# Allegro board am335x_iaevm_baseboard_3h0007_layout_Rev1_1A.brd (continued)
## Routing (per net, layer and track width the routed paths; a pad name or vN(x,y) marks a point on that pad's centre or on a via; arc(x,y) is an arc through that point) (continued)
AM335X_GPMC_AD7: length 84.1
  TOP w0.102: v2(90.6,84.2) U2.T9
  TOP w0.121: v1(141.13,94.04) 140.52,93.43 138.19,93.43 137.24,92.48 132.39,92.48 131.89,91.98 129.64,91.98 128.86,92.76 117.14,92.76 115.23,90.85 108.65,90.85 108.64,90.86 106.32,90.86 106.31,90.85 103.34,90.85 103.27,90.79 98.74,90.79 98.44,91.09 v1(98.41,91.09) ; R157.1 v1(140.63,115.73)
  LY4 w0.133: v1(98.41,91.09) 97.19,89.87 97.19,89.14 95.93,87.87 95.11,87.05 93.18,87.05 93.12,87 90.44,87 90.2,86.76 90.2,86.46 90.2,86.45 90.2,86.44 89.96,86.2 89.95,86.2 89.4,85.65 89.4,85.64 89.14,85.38 89.14,84.62 89.4,84.36 89.4,84.06 89.4,84.06 89.4,84.04 89.64,83.8 89.66,83.8 89.66,83.8 90.2,83.8 v2(90.6,84.2)
  BOTTOM w0.121: v1(141.13,94.04) 141.13,94.27 141.29,94.43 141.29,98.29 140.61,98.98 140.61,101.4 141.54,102.33 141.54,111.8 140.63,112.71 v1(140.63,115.73)
AM335X_GPMC_AD8: length 30.8
  TOP w0.102: U2.U10 91,85.41 91.35,85.76 93,85.76
  TOP w0.121: R261.2 104.94,91.1 103.28,91.1 v1(103.03,91.35) ; v1(94.02,86.35) 93.8,86.13 93.51,86.13 93.14,85.76 93,85.76
  LY3 w0.133: v1(94.02,86.35) 94.52,85.85 98.39,85.85 98.4,85.85 101.48,85.85 101.61,85.98 101.61,86.35 101.48,86.47 97.14,86.47 97.01,86.6 97.01,87.06 97.14,87.18 101.03,87.18 101.15,87.31 101.15,88.38 101.28,88.51 101.51,88.51 101.64,88.63 101.64,89.93 101.76,90.05 102.91,90.05 103.03,90.18 v1(103.03,91.35)
AM335X_GPMC_AD9: length 22.7
  TOP w0.102: U2.T10 v2(90.6,85)
  TOP w0.121: v1(102.4,91.6) 102.7,91.91 103.34,91.91 R263.2
  LY3 w0.133: v1(102.4,91.6) 102.72,91.92 103.35,91.92 103.48,91.79 103.48,87.78 103.35,87.66 103.26,87.66 103.14,87.53 103.14,86.71 102.01,85.59 99.66,85.59 99.66,85.59 94.86,85.59 94.27,85 93.69,85 93.46,85.23 90.73,85.23 90.6,85.1 v2(90.6,85)
AM335X_GPMC_AD10: length 21.8
  TOP w0.102: U2.T11 v2(90.6,86.6)
  TOP w0.121: R150.2 v1(110.17,86.78)
  BOTTOM w0.102: 93.47,86.79 92.9,86.22 91.22,86.22 90.84,86.6 v2(90.6,86.6)
  BOTTOM w0.121: v1(110.17,86.78) 109.84,86.45 104.86,86.45 104.66,86.65 96.81,86.65 96.32,87.14 95.66,87.14 95.31,86.79 93.47,86.79
AM335X_GPMC_AD11: length 45
  TOP w0.102: U2.U12 91.01,87 91.41,87.4 v2(92.2,87.4)
  TOP w0.121: v1(108.67,86.99) 108.57,86.89 108.57,84.87 108.83,84.62 109.77,84.62 R243.2
  BOTTOM w0.102: 93,87.02 92.77,86.79 92.34,86.79 92.2,86.93 v2(92.2,87.4)
  BOTTOM w0.121: v1(108.67,86.99) 108.67,88.58 108.8,88.71 109.54,88.71 109.66,88.84 109.66,90.05 109.54,90.18 107.5,90.18 107.38,90.05 107.38,86.85 107.25,86.73 105.27,86.73 105.14,86.85 105.14,88.46 105.02,88.58 104.63,88.58 104.51,88.46 104.51,87.78 104.38,87.65 103.97,87.65 103.85,87.78 103.85,88.66 103.72,88.78 103.39,88.78 103.26,88.66 103.26,87.78 103.14,87.65 102.78,87.65 102.65,87.78 102.65,88.36 102.53,88.49 98.36,88.49 98.23,88.36 98.23,87.9 98.36,87.77 100.79,87.77 100.91,87.64 100.91,87.31 100.79,87.18 97.19,87.18 97.03,87.34 97.03,88.37 96.91,88.5 95.99,88.5 95.87,88.37 95.87,87.85 95.74,87.73 95.31,87.73 94.86,87.28 93.26,87.28 93,87.02
AM335X_GPMC_AD12: length 45.1
  TOP w0.102: U2.T12 v2(90.6,87.4)
  TOP w0.121: v1(111.39,87.13) 111.75,86.78 R152.2
  LY4 w0.133: v1(101.69,88.05) 101.69,87.98 101.81,87.86 105.14,87.86 105.27,87.98 105.27,88.51 105.14,88.63 101.81,88.63 101.69,88.76 101.69,89.14 101.81,89.27 108.19,89.27 108.32,89.14 108.32,88.63 108.19,88.51 107.38,88.51 107.25,88.38 107.25,87.77 107.38,87.64 109.95,87.64 110.08,87.77 110.08,89.83 109.95,89.95 109.28,89.95 109.16,90.08 109.16,90.54 109.28,90.66 110.81,90.66 111.07,90.4 111.07,87.45 v1(111.39,87.13)
  BOTTOM w0.102: 92.75,86.55 91.45,86.55 v2(90.6,87.4)
  BOTTOM w0.121: v1(101.69,88.05) 101.28,87.64 101.28,87.06 101.12,86.9 96.91,86.9 96.79,87.03 96.79,88.1 96.66,88.23 96.24,88.23 96.12,88.1 96.12,87.61 95.99,87.48 95.43,87.48 94.99,87.04 93.37,87.04 92.88,86.55 92.75,86.55
AM335X_GPMC_AD13: length 21.8
  TOP w0.102: v2(89.8,87.4) U2.R12
  TOP w0.121: v1(96.48,90.38) 96.53,90.38 97.04,89.88 R247.2
  BOTTOM w0.102: 93,88.71 92.9,88.71 92.77,88.58 92.77,87.97 92.65,87.84 92.26,87.84 92.14,87.97 92.14,88.84 92.01,88.96 91.35,88.96 91.22,88.84 91.22,87.95 91.1,87.82 90.21,87.82 89.8,87.41 v2(89.8,87.4)
  BOTTOM w0.121: v1(96.48,90.38) 96.48,91.41 96.61,91.53 98.67,91.53 98.79,91.66 98.79,92.21 98.67,92.34 96.1,92.34 95.52,91.76 95.52,88.43 94.93,87.84 94.04,87.84 93.92,87.97 93.92,88.58 93.79,88.71 93,88.71
AM335X_GPMC_AD14: length 12.3
  TOP w0.102: U2.V13 92.83,87.8 93,87.97
  TOP w0.121: 93,87.97 93,87.97 94.78,87.97 95.77,88.97 95.77,90.79 98.14,93.16 99.23,93.16 100.34,94.27 R248.2
AM335X_GPMC_AD15: length 10.6
  TOP w0.102: U2.U13 91.42,88.22 93,88.22
  TOP w0.121: 93,88.22 94.68,88.22 95.53,89.07 95.53,90.95 96.56,91.99 96.56,93.46 R253.2
AM335X_GPMC_ADVN_ALE: length 62.6
  TOP w0.102: v2(89.8,82.6) U2.R7
  TOP w0.121: v1(139.51,97.67) 140.12,98.28 R137.2
  BOTTOM w0.102: v2(89.8,82.6) 89.8,82.55 90.17,82.18 91.27,82.18
  BOTTOM w0.121: 91.27,82.18 91.86,82.77 96.01,82.77 98,84.75 98,85.15 98.02,85.18 98.02,85.19 98.24,85.41 98.63,85.41 98.83,85.21 111.71,85.21 115.17,88.67 115.58,88.67 129.12,88.67 129.88,89.43 131.09,89.43 131.68,88.84 137.4,88.84 138.79,90.24 138.79,96.96 v1(139.51,97.67)
AM335X_GPMC_BE0N_CLE: length 59.3
  TOP w0.102: v2(90.6,81.8) U2.T6
  TOP w0.121: R136.2 140.12,95.72 v1(139.61,95.21)
  BOTTOM w0.102: 91.92,82.52 91.2,81.8 v2(90.6,81.8)
  BOTTOM w0.121: 91.92,82.52 96.11,82.52 97.29,83.7 97.79,83.7 98.81,84.72 112.19,84.72 115.64,88.18 129.32,88.18 130.09,88.94 130.77,88.94 131.36,88.35 137.6,88.35 139.29,90.03 139.29,94.89 v1(139.61,95.21)
AM335X_GPMC_BE1N: length 79.9
  TOP w0.102: 91,92.9 U2.U18
  TOP w0.121: 91,92.9 91,93.59 92.83,95.42 94.83,95.42 95.06,95.64 v1(96.18,95.64) ; v1(97.62,141.9) 97.57,141.95 R577.2
  LY4 w0.133: v1(96.18,95.64) 96.18,97.98 95.87,98.28 95.87,111.09 96,111.21 96.4,111.21 96.53,111.09 96.53,104.23 96.66,104.1 97.01,104.1 97.14,104.23 97.14,111.72 97.01,111.85 96.4,111.85 96.26,112 96.26,114.04 95.67,114.63 95.67,128.92 95.03,129.55 95.03,140.75 94.8,140.98 93,140.98 92.87,141.11 92.87,143.04 93,143.17 96.35,143.17 v1(97.62,141.9)
AM335X_GPMC_CLK: length 73.4
  TOP w0.102: 93.89,87.54 93.26,87.54 92.72,87 U2.V12
  TOP w0.121: R572.2 116.69,95.36 116.81,95.49 117.26,95.49 117.39,95.62 117.39,96 117.26,96.13 116.32,96.13 116.19,96 116.19,95.54 116.06,95.41 115.78,95.41 115.66,95.54 115.66,96 115.53,96.13 115.1,96.13 114.98,96 114.98,94.55 114.85,94.42 114.46,94.42 114.34,94.55 114.34,96 114.21,96.13 113.7,96.13 113.58,96 113.58,94.55 113.45,94.42 112.97,94.42 112.84,94.55 112.84,96 112.71,96.13 112.36,96.13 112.23,96 112.23,94.55 112.1,94.42 111.67,94.42 111.54,94.55 111.54,96 111.42,96.13 111.06,96.13 110.93,96 110.93,94.55 110.81,94.42 110.5,94.42 110.37,94.55 110.37,96 110.25,96.13 109.92,96.13 109.79,96 109.79,94.53 109.66,94.4 109.42,94.4 109.29,94.53 109.29,96 109.16,96.13 107.89,96.13 107.76,96 107.76,95.41 107.89,95.29 108.19,95.29 108.32,95.16 108.32,94.52 108.19,94.39 107.3,94.39 107.17,94.52 107.17,96 107.05,96.13 106.72,96.13 106.59,96 106.59,94.52 106.46,94.39 106.13,94.39 106,94.52 106,95.99 105.87,96.11 105.24,96.11 105.12,95.99 105.12,94.01 104.99,93.88 104.61,93.88 104.48,94.01 104.48,95.92 104.35,96.05 104.02,96.05 103.89,95.92 103.89,94.18 103.77,94.05 103.44,94.05 103.31,94.18 103.31,94.58 103.19,94.7 102.88,94.7 102.75,94.58 102.75,93.18 102.88,93.05 103.35,93.05 103.47,92.92 103.47,92.39 103.35,92.27 101.76,92.27 101.64,92.14 100.04,92.14 99.91,92.01 99.91,91.73 100.04,91.6 101.61,91.6 101.74,91.48 101.74,91.16 101.61,91.04 99.5,91.04 99.38,91.16 99.38,92.7 99.25,92.82 98.97,92.82 98.84,92.7 98.84,91.66 98.72,91.53 98.39,91.53 98.26,91.66 98.26,92.24 98.13,92.37 97.75,92.37 97.62,92.24 97.62,91.66 97.5,91.53 96.92,91.53 96.02,90.64 96.02,88.48 95.34,87.8 95.34,87.51 95.11,87.29 94.59,87.29 94.34,87.54 93.89,87.54
AM335X_GPMC_CS0N: length 58.4
  TOP w0.102: 93,82.2 U2.V6
  TOP w0.121: 93,82.2 93.06,82.26 95.79,82.26 98.44,84.91 v1(98.44,84.97) ; R183.2 140.12,96.99 v1(139.56,96.43)
  BOTTOM w0.121: v1(139.56,96.43) 139.04,95.91 139.04,90.13 137.5,88.59 131.57,88.59 130.98,89.18 129.98,89.18 129.22,88.42 115.47,88.42 115.27,88.42 111.81,84.97 98.73,84.97 98.72,84.97 v1(98.44,84.97)
AM335X_GPMC_CS1N: length 13.3
  TOP w0.102: U2.U9 91.01,84.6 91.41,85 92.19,85
  TOP w0.121: R175.1 99.99,89.6 v1(100.42,90.03) ; 92.19,85 92.34,84.85 94.96,84.85 v1(95.25,85.14)
  LY4 w0.133: v1(95.25,85.14) 95.25,85.28 97.93,87.96 99.18,87.96 99.66,88.43 99.66,89.27 v1(100.42,90.03)
AM335X_GPMC_CS2N: length 16.9
  TOP w0.121: R173.1 100.49,92.87 v1(100.49,93.41) ; v1(95.38,84.2) 95.38,84.21 95.35,84.24 95.35,84.34 95.09,84.6 U2.V9
  LY4 w0.133: v1(100.49,93.41) 100.49,91.91 100.87,91.54 100.87,89.17 99.16,87.46 97.94,87.46 95.92,85.44 95.92,84.74 v1(95.38,84.2)
AM335X_GPMC_CS3N: length 75.5
  TOP w0.102: v2(90.6,88.2) U2.T13
  TOP w0.121: v1(94.93,145.78) 94.88,145.83 93.94,145.83 R573.2
  LY4 w0.102: v2(90.6,88.2) 93.3,88.2
  LY4 w0.133: 93.3,88.2 93.4,88.3 95.38,88.3 96.03,88.95 96.03,90.57 96.75,91.29 97.97,91.29 99.48,92.79 99.48,93.64 100.05,94.2 100.05,100.59 100.95,101.5 100.95,116.99 102.04,118.08 102.04,120.01 101.54,120.51 101.54,132.85 101.42,132.98 99.4,132.98 99.27,133.11 99.27,135.62 99.4,135.75 101.24,135.75 101.54,136.05 101.54,140.79 97.12,145.22 95.49,145.22 v1(94.93,145.78)
AM335X_GPMC_OEN_REN: length 67.8
  TOP w0.102: v2(90.6,82.6) U2.T7
  TOP w0.121: R134.2 140.11,104.16 v1(140.11,103.47)
  BOTTOM w0.102: v2(90.6,82.6) 91.02,83.02 93,83.02
  BOTTOM w0.121: 93,83.02 95.91,83.02 97.75,84.86 97.75,85.26 97.76,85.27 97.76,85.38 98.04,85.66 98.73,85.66 98.93,85.46 111.61,85.46 115.06,88.92 115.68,88.92 129.02,88.92 129.78,89.68 131.25,89.68 131.84,89.09 137.3,89.09 138.55,90.34 138.55,98.61 137.81,99.35 137.81,100.42 140.11,102.72 v1(140.11,103.47)
AM335X_GPMC_WAIT: length 61
  TOP w0.102: U2.T17 90.24,91 90.59,91.35 90.59,92.9
  TOP w0.121: 90.59,92.9 90.59,93.89 92.37,95.67 93.59,95.67 94.2,96.27 94.2,97.08 95.26,98.14 95.26,100.94 95.87,101.56 107.78,101.56 108.01,101.33 124.14,101.33 125.34,102.53 130.47,102.53 131.74,103.8 131.74,104.46 132.49,105.21 136.24,105.21 137.6,103.85 138.71,103.85 138.89,103.67 139.23,103.67 R179.2
AM335X_GPMC_WEN: length 70
  TOP w0.102: U2.U6 91.03,82.2 91.41,82.59 92.08,82.59
  TOP w0.121: 92.08,82.59 92.16,82.51 95.68,82.51 96.49,83.32 96.49,84.23 v1(96.51,84.24) ; R138.2 v1(139.61,104.99)
  BOTTOM w0.121: v1(139.61,104.99) 139.1,104.48 139.1,102.76 137.01,100.68 137.01,98.97 137.63,98.35 137.63,92.09 137.8,91.91 137.8,90.65 136.99,89.83 132.29,89.83 131.7,90.42 129.47,90.42 128.71,89.66 114.76,89.66 111.3,86.2 99.24,86.2 99.04,86.4 97.68,86.4 97.55,86.28 96.31,86.28 96,85.97 95.99,85.97 95.8,85.77 95.8,84.94 96.49,84.25 96.51,84.25 v1(96.51,84.24)
AM335X_GPMC_WPN: length 55.7
  TOP w0.102: U2.U17 91.38,91.38 91.38,92.9
  TOP w0.121: R180.2 139.61,102.02 137.83,102.02 137.39,102.46 137.39,102.69 137.16,102.92 132.71,102.92 130.05,100.25 129.91,100.11 114.34,100.11 112.81,98.58 104.23,98.58 102.45,96.8 98.07,96.8 96.44,95.17 95.32,95.17 94.86,94.7 93.1,94.7 91.38,92.98 91.38,92.9
AM335X_I2C0_SCL: length 201.1
  TOP w0.102: v2(79.4,90.6) U2.C16
  TOP w0.121: R265.2 145.33,71.28 143.93,71.28 142.66,72.55 141.52,72.55 140.94,71.98 U7.6 140.94,68.76 140.52,68.34 126.02,68.34 120.41,62.73 120.41,59.81 116.97,56.36 107.29,56.36 105.51,54.58 100.99,54.58 100.93,54.52 100.57,54.52 100.5,54.58 97.98,54.58 97.22,53.82 96.07,53.82 95.34,53.08 85.72,53.08 85.3,52.67 83.9,52.67 83.39,53.18 80.65,53.18 80.02,53.82 79.02,53.82 v1(78.57,53.37) 78.13,53.37 77.94,53.18 74.63,53.18 73.05,54.76 73.05,55.35 72.5,55.9 72.13,55.9 71.72,55.9 71.07,55.25 66.59,55.25 64.48,57.35 64.34,57.5 61.63,57.5 60.24,58.89 v1(60.24,59.79) ; v1(77.86,95.41) 75.48,95.41 75.07,95.82 73.49,95.82 72.96,95.29 71.74,95.29 69.69,97.35 66.37,97.35 65.42,97.35 64.82,96.75 62.81,96.75 62.62,96.94 v1(62.01,96.94)
  LY4 w0.133: v1(80.68,25.56) 80.68,26.07 81.31,26.7 81.31,36.25 80.8,36.76 80.8,43.24 78.77,45.27 78.77,53.18 v1(78.57,53.37)
  BOTTOM w0.102: v2(79.4,90.6) 79.4,90.6 79.79,90.99 79.79,92.9
  BOTTOM w0.121: R551.2 81.19,25.06 v1(80.68,25.56) ; 79.79,92.9 79.79,94.23 78.94,95.08 78.17,95.08 77.86,95.39 v1(77.86,95.41) 78.29,95.84 78.29,96.84 78.52,97.07 ; v1(60.24,59.79) 60.55,60.11 60.55,61.12 60.36,61.31 60.36,69.22 63.32,72.17 63.61,72.46 63.61,81.42 63.22,81.8 63.22,83.05 62.56,83.71 62.56,86.8 61.84,87.52 61.84,88.66 60.74,89.76 60.74,91.1 61.51,91.86 61.51,96.15 62.01,96.66 v1(62.01,96.94)
AM335X_I2C0_SDA: length 210
  TOP w0.102: 79.67,93.1 79.67,92.14 79.41,91.88 79.41,91.39 U2.C17
  TOP w0.121: 79.67,93.1 79.67,94.33 79.03,94.97 79.03,95.27 78.18,96.13 v1(77.84,96.13) 77.81,96.13 77.35,95.66 75.97,95.66 75.55,96.07 73.39,96.07 72.86,95.55 72.24,95.55 72.23,95.54 71.85,95.54 69.79,97.6 66.47,97.6 65.18,97.6 64.59,97.01 63.28,97.01 62.79,97.5 61.89,97.5 61.51,97.13 58.88,97.13 55.79,94.05 v1(54.52,94.05) ; v1(54.52,60.04) 54.53,60.04 59.09,60.04 59.6,59.52 59.6,59.09 61.44,57.25 64.24,57.25 66.5,54.98 71.15,54.98 71.82,55.65 72.39,55.65 72.8,55.25 72.8,54.66 73.06,54.39 74.52,52.93 79.15,52.93 v1(79.59,53.37) 79.84,53.12 80.15,53.12 80.34,52.93 83.29,52.93 83.8,52.42 85.5,52.42 85.92,52.84 95.45,52.84 96.18,53.57 97.32,53.57 98.09,54.34 100.4,54.34 100.46,54.28 105.55,54.28 107.39,56.11 117.18,56.11 120.66,59.6 120.66,62.29 126.45,68.08 141.77,68.08 142.21,68.53 U7.5 142.21,71.98 142.4,72.17 142.66,72.17 143.8,71.03 145.33,71.03 R268.2
  LY4 w0.133: v1(79.59,53.37) 79.03,52.82 79.03,45.38 81.06,43.34 81.06,36.87 81.57,36.36 v1(81.57,25.82)
  BOTTOM w0.121: R550.2 81.95,26.2 v1(81.57,25.82) ; v1(77.84,96.13) 77.84,96.61 77.38,97.07 ; v1(54.52,94.05) 54.52,91.6 55.32,90.8 55.32,88.16 54.04,86.88 54.04,85.99 53.44,85.39 53.44,80.68 51.6,78.84 51.6,74.65 54.71,71.54 54.71,60.23 v1(54.52,60.04)
AM335X_LCD_AC_BIAS_EN: length 68.7
  TOP w0.102: v2(89.8,81.8) U2.R6
  TOP w0.121: v1(97.45,83.22) 97.79,83.57 99.07,83.57 v1(99.41,83.23) ; R273.2 127.16,75.22 125.77,75.22 v1(125.77,75.21)
  BOTTOM w0.102: 93.72,80.76 93.71,80.76 91.65,80.76 90.99,81.42 90.44,81.42 90.06,81.8 v2(89.8,81.8)
  BOTTOM w0.121: v1(97.45,83.22) 96.48,82.26 94.73,82.26 94.14,81.68 94.14,81.19 93.72,80.76 ; v1(125.77,75.21) 124.5,75.21 124.37,75.34 124.37,77.63 125.33,78.59 125.33,79.09 125.01,79.41 124.37,79.41 123.74,80.05 123.74,82.99 123.61,83.12 122.64,83.12 122.52,82.99 122.52,81.98 122.39,81.85 113.04,81.85 112.91,81.98 112.91,82.36 113.04,82.49 121.32,82.49 121.45,82.61 121.45,82.99 121.32,83.12 105.85,83.12 105.73,83.25 105.73,83.35 105.6,83.48 99.66,83.48 v1(99.41,83.23)
AM335X_LCD_DATA0: length 118.9
  TOP w0.102: 92.92,77.38 91.94,77.38 91.93,77.37 90.78,77.37 90.51,77.63 90.01,77.63 89.45,78.2 U2.R1
  TOP w0.121: v1(136.26,71.03) 135.81,70.59 118.32,70.59 118.11,70.8 113.63,70.8 112.17,72.26 106.46,72.26 104.92,73.79 98.79,73.79 96.35,76.23 95.68,76.23 94.53,77.38 92.92,77.38 ; SW3.16 v1(162.5,69.13) ; R240.2 141.38,86.52 142.65,86.52 v1(142.66,86.52) 146.29,86.52 146.67,86.91 151.26,86.91 151.58,86.59 153.01,86.59 153.96,87.54 v1(166.53,87.54)
  BOTTOM w0.121: v1(142.66,86.52) 142.15,86.52 141.29,85.67 141.29,80.49 138.27,77.46 138.27,74.75 135.83,72.32 135.83,71.47 135.87,71.43 135.87,71.42 v1(136.26,71.03) ; v1(166.53,87.54) 166.53,87.41 166.09,86.97 166.09,84.54 166.34,84.29 166.34,73.79 165.42,72.87 164.32,72.87 164.06,72.61 164.06,69.57 R96.1 v1(162.5,69.13)
AM335X_LCD_DATA1: length 115.6
  TOP w0.102: U2.R2 89.4,78.76 89.87,78.29 89.87,78.06 90.08,77.85 90.6,77.85 90.84,77.61 92.15,77.61 92.15,77.61
  TOP w0.121: v1(161.45,88.18) 161.38,88.1 153.71,88.1 153.68,88.07 143.06,88.07 v1(142.53,87.54) 142.53,87.54 141.38,87.54 R241.2 ; SW3.15 v1(162.5,66.59) ; v1(135.42,71.03) 134.96,71.03 134.81,70.88 118.74,70.88 118.55,71.07 113.73,71.07 112.31,72.5 106.56,72.5 105.02,74.04 98.89,74.04 96.45,76.48 95.81,76.48 94.59,77.7 92.89,77.7 92.8,77.61 92.16,77.61 92.15,77.61 92.15,77.61
  BOTTOM w0.102: 138.02,74.85 135.6,72.43 135.6,71.51 135.42,71.33
  BOTTOM w0.121: v1(135.42,71.03) 135.42,71.33 ; v1(161.45,88.18) 161.45,84.23 161.51,84.17 161.51,83.92 162.02,83.42 162.02,82.45 161.52,81.95 161.52,67.56 v1(162.5,66.59) R97.1 ; v1(142.53,87.54) 141.05,86.05 141.05,80.59 138.02,77.57 138.02,74.85
AM335X_LCD_DATA2: length 121.9
  TOP w0.102: v2(89.8,79.4) U2.R3
  TOP w0.121: v1(136.79,71.91) 136.49,71.91 136.36,72.04 136.36,72.3 136.23,72.43 135.72,72.43 135.6,72.3 135.6,71.97 135.47,71.84 135.04,71.84 134.91,71.97 134.91,72.3 134.78,72.43 134.17,72.43 134.05,72.3 134.05,71.59 133.92,71.46 124.4,71.46 124.27,71.59 124.27,72.45 124.14,72.58 120.14,72.58 119.7,73.03 114.42,73.03 112.63,74.82 99.19,74.82 98.08,75.93 v1(98.08,76.24) ; SW3.14 v1(162.5,64.05) ; R245.2 141.38,84.11 v1(142.53,84.11) 143.83,84.11 143.9,84.17 152.63,84.17 153.96,85.51 v1(166.66,85.51)
  BOTTOM w0.102: v2(89.8,79.4) 89.8,78.57 90.76,77.62 92.95,77.62 93,77.57
  BOTTOM w0.121: v1(162.5,64.05) R98.1 164.71,65.14 166.36,65.14 166.66,65.44 v1(166.66,85.51) ; v1(136.79,71.91) 136.81,71.91 137.23,72.33 137.23,73.01 138.76,74.54 138.76,76.09 140.9,78.22 140.9,78.86 141.79,79.76 141.79,83.63 142.15,83.98 142.41,83.98 v1(142.53,84.11) ; 93,77.57 94.62,77.57 95.44,76.75 97.57,76.75 v1(98.08,76.24)
AM335X_LCD_DATA3: length 126
  TOP w0.102: U2.R4 v2(89.8,80.2)
  TOP w0.121: v1(166.53,86.52) 165.86,85.85 153.28,85.85 152.88,85.44 142.79,85.44 142.66,85.31 v1(142.66,85.25) 142.53,85.13 141.39,85.13 R246.2 ; v1(136.79,72.53) 136.76,72.53 136.46,72.83 120.25,72.83 119.8,73.27 114.53,73.27 113.31,74.49 113.31,74.5 112.75,75.07 99.57,75.07 v1(98.72,75.92) ; SW3.13 v1(162.5,61.51)
  BOTTOM w0.102: v2(89.8,80.2) 89.8,79.94 90.18,79.56 90.18,78.99 90.22,78.96 90.22,78.44 90.44,78.22 90.45,78.22 90.85,77.82 92.93,77.82 93,77.89
  BOTTOM w0.121: v1(136.79,72.53) 136.75,72.53 136.79,72.57 136.79,72.92 138.51,74.65 138.51,76.19 140.65,78.33 140.65,78.96 141.54,79.85 141.54,84.14 v1(142.66,85.25) ; 93,77.89 94.65,77.89 95.54,77 98.08,77 98.72,76.36 v1(98.72,75.92) ; v1(162.5,61.51) R99.1 164.58,60.54 166.23,60.54 167.1,61.41 167.1,85.96 v1(166.53,86.52)
AM335X_LCD_DATA4: length 118.9
  TOP w0.102: 93,77.95 92.84,77.95 92.71,77.82 92.39,77.82 92.39,77.82 90.91,77.82 90.53,78.2 U2.T1
  TOP w0.121: R251.2 141.39,81.06 142.28,81.06 v1(142.66,81.44) 143,81.44 143.52,81.96 152.16,81.96 152.74,81.38 153.15,81.38 154.23,82.46 161.07,82.46 v1(161.58,82.97) ; SW3.12 v1(162.5,58.97) ; v1(138.72,73.06) 137.13,71.47 134.65,71.47 134.31,71.13 119,71.13 118.81,71.32 114.03,71.32 113.91,71.45 113.91,71.79 114.03,71.92 116.39,71.92 116.52,72.05 116.52,72.4 116.39,72.53 113.9,72.53 113.52,72.91 106.52,72.91 106.39,73.04 106.39,74.16 106.27,74.29 98.99,74.29 96.46,76.82 95.82,76.82 94.68,77.95 93,77.95
  BOTTOM w0.121: R100.1 v1(162.5,58.97) 161.03,60.44 161.03,78.45 160.63,78.85 160.63,81.41 161.58,82.36 v1(161.58,82.97) ; v1(142.66,81.44) 142.66,79.92 141.39,78.65 141.39,78.02 139.26,75.88 139.26,74.26 139.16,74.17 139.16,73.5 138.9,73.24 138.9,73.24 v1(138.72,73.06)
AM335X_LCD_DATA5: length 120.9
  TOP w0.102: v2(90.6,78.6) U2.T2
  TOP w0.121: v1(137.68,72.83) 137.64,72.8 137.15,72.8 136.87,73.07 120.35,73.07 119.9,73.52 118.12,73.52 117.99,73.65 117.99,74.62 117.87,74.75 117.46,74.75 117.33,74.62 117.33,73.65 117.21,73.52 116.9,73.52 116.78,73.65 116.78,74.62 116.65,74.75 116.24,74.75 116.12,74.62 116.12,73.7 115.99,73.57 115.58,73.57 115.45,73.7 115.45,74.62 115.33,74.75 114.9,74.75 114.77,74.62 114.77,74.05 114.64,73.93 114.31,73.93 114.18,74.05 114.18,74.62 114.06,74.75 113.56,74.75 113.44,74.88 113.44,75.19 113.31,75.32 100.08,75.32 98.53,76.87 97.11,76.87 96.47,77.51 v1(96.11,77.51) ; SW3.11 v1(162.5,56.43) ; v1(161.07,83.98) 159.93,82.84 153.07,82.84 152.69,82.46 v1(142.66,82.46) 142.28,82.08 141.39,82.08 R252.2
  BOTTOM w0.102: v2(90.6,78.6) 91.46,78.6 91.48,78.58 91.64,78.58 91.64,78.58 92.39,78.58 92.39,78.58 92.68,78.58 92.73,78.53 93,78.53
  BOTTOM w0.121: v1(142.66,82.46) 142.07,81.88 142.07,79.69 141.14,78.76 141.14,78.12 139.01,75.99 139.01,74.44 137.68,73.11 v1(137.68,72.83) ; R101.1 v1(162.5,56.43) 160.78,58.14 160.78,78.35 160.38,78.75 160.38,81.51 161.07,82.2 v1(161.07,83.98) ; 93,78.53 95.09,78.53 v1(96.11,77.51)
AM335X_LCD_DATA6: length 130
  TOP w0.102: v2(90.6,79.4) U2.T3
  TOP w0.121: v1(131.36,60.74) 137.32,60.74 137.95,61.37 150.54,61.37 151.65,60.26 158.15,60.26 161.84,56.57 161.84,54.55 v1(162.5,53.89) SW3.10 ; R270.2 127.16,77.25 125.63,77.25 125.57,77.31 124.94,77.31 v1(124.88,77.38) 124.88,78.23 124.75,78.35 124.42,78.35 124.29,78.23 124.29,77.18 124.17,77.05 114.26,77.05 114.13,77.18 114.13,77.63 114.26,77.76 122.49,77.76 122.62,77.89 122.62,78.32 122.49,78.45 113.58,78.45 113.45,78.32 113.45,77.58 113.32,77.46 109.03,77.46 108.9,77.33 108.9,76.92 109.03,76.8 113.14,76.8 113.27,76.67 113.27,76.43 113.14,76.31 102.1,76.31 101.83,76.58 100.35,76.58 99.41,77.51 99.41,78.72 v1(99.61,78.91)
  BOTTOM w0.102: 92.9,78.82 92.89,78.83 92.58,78.83 92,79.4 v2(90.6,79.4) ; 93.38,78.79 93.24,78.79
  BOTTOM w0.121: v1(124.88,77.38) 124.88,76.36 125.45,75.8 125.83,75.8 126.4,75.22 127.67,75.22 128.04,74.85 128.04,74.59 131.36,71.28 v1(131.36,60.74) ; R102.1 v1(162.5,53.89) ; 92.9,78.82 93.07,78.82 93.1,78.79 93.24,78.79 93.25,78.78 93.49,78.78 ; v1(99.61,78.91) 95.54,78.91 95.41,78.78 93.49,78.78 ; 93.49,78.78 93.48,78.79 93.38,78.79
AM335X_LCD_DATA7: length 139.1
  TOP w0.102: v2(90.6,80.2) U2.T4
  TOP w0.121: v1(102.65,77.38) 102.97,77.07 107.81,77.07 107.94,77.19 107.94,80.61 107.81,80.73 104.23,80.73 104.1,80.86 104.1,81.32 104.23,81.44 108.93,81.44 109.05,81.32 109.05,80.81 109.18,80.68 114.03,80.68 114.16,80.81 114.16,82.79 114.29,82.92 114.95,82.92 115.07,82.79 115.07,80.81 115.2,80.68 115.66,80.68 115.78,80.81 115.78,83.07 115.91,83.2 119.72,83.2 119.85,83.07 119.85,82.69 119.72,82.56 116.27,82.56 116.14,82.43 116.14,82.08 116.27,81.95 121.53,81.95 121.65,82.08 121.65,82.49 121.53,82.61 120.66,82.61 120.53,82.74 120.53,83.07 120.66,83.2 122.57,83.2 122.97,82.79 v1(122.97,82.33) 125.39,82.33 125.39,82.33 127.16,82.33 R259.2 ; v1(128.56,63.84) 128.02,63.3 128.02,61.47 129.77,59.72 137.19,59.72 138.59,61.12 150.38,61.12 151.51,59.99 158.06,59.99 161.58,56.48 161.58,52.26 v1(162.5,51.35) SW3.9
  BOTTOM w0.102: 93,80.02 90.79,80.02 90.61,80.2 v2(90.6,80.2)
  BOTTOM w0.121: 93,80.02 95.19,80.02 95.35,79.86 97.01,79.86 97.27,79.6 99.89,79.6 100.29,79.19 100.29,78.99 100.29,78.72 100.95,78.07 101.96,78.07 v1(102.65,77.38) ; v1(128.56,63.84) 128.05,64.35 128.05,65.82 122.97,70.9 v1(122.97,82.33) ; R103.1 v1(162.5,51.35)
AM335X_LCD_DATA8: length 145.1
  TOP w0.102: U2.U1 91.15,78.2 91.6,78.65 92.68,78.65
  TOP w0.121: SW4.16 v1(162.47,91.73) ; v1(159.93,63.28) 159.07,63.28 158.48,62.69 153.12,62.69 152.78,63.04 138.11,63.04 137.92,63.22 134.86,63.22 134.73,63.34 129.87,63.34 v1(128.56,64.65) ; R262.2 127.16,80.3 125.45,80.3 125.32,80.17 125.32,79.67 124.94,79.29 v1(123.86,79.29) ; v1(123.83,71.57) 123.83,72.17 123.7,72.3 123.05,72.3 122.92,72.17 122.92,71.7 122.8,71.57 122.41,71.57 122.29,71.7 122.29,72.1 122.16,72.22 121.73,72.22 121.6,72.1 121.6,71.5 121.47,71.38 120.94,71.38 120.81,71.5 120.81,72.2 120.69,72.33 120.26,72.33 120.13,72.2 120.13,71.5 120,71.38 119.67,71.38 119.54,71.5 119.54,72.65 119.42,72.78 118.96,72.78 118.83,72.65 118.83,71.7 118.71,71.57 118.32,71.57 118.2,71.7 118.2,72.65 118.07,72.78 117.59,72.78 117.46,72.65 117.46,71.72 117.33,71.59 116.93,71.59 116.8,71.72 116.8,72.65 116.67,72.78 114.16,72.78 113.78,73.16 106.77,73.16 106.64,73.29 106.64,73.8 106.77,73.93 112.56,73.93 112.69,74.05 112.69,74.41 112.56,74.54 99.09,74.54 96.56,77.07 95.92,77.07 94.38,78.6 92.73,78.6 92.68,78.65
  BOTTOM w0.121: v1(159.93,63.28) 159.93,78.5 159.89,78.54 159.89,89.15 v1(162.47,91.73) R104.1 ; v1(128.56,64.65) 128.56,65.95 127.67,66.84 127.67,70.01 126.12,71.57 v1(123.83,71.57) 123.83,79.25 v1(123.86,79.29)
AM335X_LCD_DATA9: length 155.3
  TOP w0.102: 93,79.1 92.97,79.13 92.75,79.13 92.53,79.35 91.41,79.35 91.07,79 U2.U2
  TOP w0.121: SW4.15 v1(162.47,89.19) ; R266.2 127.16,78.27 125.39,78.27 v1(124.88,78.78) 124.14,78.78 124.01,78.65 124.01,77.42 123.89,77.3 123.07,77.3 122.95,77.42 122.95,78.65 122.82,78.78 118.02,78.78 117.89,78.9 117.89,79.26 118.02,79.39 123.05,79.39 123.18,79.51 123.18,79.93 123.05,80.05 114.08,80.05 113.96,79.93 113.96,79.64 114.08,79.51 116.78,79.51 116.9,79.39 116.9,79.01 116.78,78.88 108.72,78.88 108.6,78.75 108.6,78.4 108.72,78.27 113.07,78.27 113.2,78.14 113.2,77.83 113.07,77.7 108.75,77.7 108.65,77.61 108.65,76.68 108.53,76.55 102.23,76.55 101.96,76.82 100.73,76.82 v1(99.86,77.7) ; v1(97.32,77.63) 96.68,78.27 95.51,78.27 94.68,79.1 93,79.1 ; v1(160.31,61.63) 159.22,60.54 151.83,60.54 150.74,61.63 v1(128.82,61.63)
  BOTTOM w0.121: v1(99.86,77.7) 97.89,77.7 97.83,77.63 v1(97.32,77.63) ; v1(128.82,61.63) 129.07,61.89 129.07,65.95 128.05,66.97 128.05,71.54 127.8,71.79 127.16,71.79 126.78,72.17 126.78,73.32 126.21,73.89 125.47,73.89 124.12,75.25 124.12,78.02 v1(124.88,78.78) ; v1(160.31,61.63) 160.31,63.04 160.37,63.1 160.37,78.41 160.14,78.64 160.14,87.48 161.85,89.19 v1(162.47,89.19) R105.1
AM335X_LCD_DATA10: length 102.6
  TOP w0.102: U2.U3 91.04,79.8 91.41,80.17 93,80.17
  TOP w0.121: v1(161.96,78.02) 150.34,78.02 150.09,78.27 147.87,78.27 147.24,78.9 142.66,78.9 v1(142.66,78.9) 141.52,78.9 R256.2 ; v1(104.16,73.09) 104.16,72.13 104.29,72.01 112.05,72.01 112.18,71.88 112.18,71.46 112.05,71.33 109.66,71.33 109.54,71.21 109.54,70.68 109.66,70.55 117.48,70.55 117.7,70.34 136.35,70.34 138.44,72.43 v1(138.72,72.43) ; v1(96.68,79.35) 95.86,80.17 93,80.17 ; SW4.14 v1(162.47,86.65)
  BOTTOM w0.121: v1(96.68,79.35) 99.79,79.35 100.05,79.09 100.05,78.59 100.82,77.82 100.82,77.82 101.18,77.82 101.89,77.12 101.89,76.94 104.16,74.66 v1(104.16,73.09) ; R106.1 v1(162.47,86.65) 162.03,86.21 162.03,83.76 162.27,83.52 162.27,82.35 161.78,81.86 161.78,78.75 161.96,78.56 v1(161.96,78.02) ; v1(142.66,78.9) 142.66,78.46 139.74,75.54 139.74,73.7 139.17,73.13 139.17,72.67 138.92,72.43 v1(138.72,72.43)
AM335X_LCD_DATA11: length 102.5
  TOP w0.102: U2.U4 91.01,80.6 91.41,81 91.86,81 91.93,80.93 91.94,80.93 92.19,80.68 92.59,80.68
  TOP w0.121: 92.59,80.68 94.53,80.68 94.84,81 v1(95.41,81) ; SW4.13 v1(162.47,84.11) ; v1(139.61,72.94) 139.61,73.42 139.53,73.5 138.54,73.5 138.36,73.32 120.45,73.32 120,73.77 118.43,73.77 118.31,73.9 118.31,74.28 118.43,74.41 120.76,74.41 120.89,74.54 120.89,74.87 120.76,75 113.81,75 113.68,75.13 113.68,75.44 113.56,75.56 100.28,75.56 98.46,77.38 98.46,78.27 98.27,78.46 98.27,80.49 v1(98.65,80.87) ; v1(162.34,75.35) 160.18,77.51 150.15,77.51 150.09,77.57 v1(142.66,77.57) 142.17,77.57 142.11,77.63 141.38,77.63 R267.2
  BOTTOM w0.121: v1(142.66,77.57) 142.15,77.57 140.25,75.67 140.25,73.57 v1(139.61,72.94) ; v1(98.65,80.87) 98.48,80.87 98.18,80.56 96.62,80.56 96.19,81 v1(95.41,81) ; R107.1 v1(162.47,84.11) 162.47,83.67 162.52,83.62 162.52,82.24 162.03,81.75 162.03,78.85 162.4,78.47 162.4,77.57 162.03,77.19 162.03,76.04 162.34,75.73 v1(162.34,75.35)
AM335X_LCD_DATA12: length 94.7
  TOP w0.102: U2.V2 92.57,79 ; 138.04,80.81 135.17,80.81
  TOP w0.121: 135.17,80.81 134.91,80.81 v1(134.28,80.17) ; v1(97.89,81.36) 97.89,81.35 97.89,77.44 97.64,77.19 97.14,77.19 96.38,77.95 95.48,77.95 94.58,78.85 92.87,78.85 92.8,78.91 92.66,78.91 92.57,79 ; 138.04,80.81 138.9,80.81 139.16,80.55 139.16,80.49 139.61,80.05 140.37,80.05 R257.2 141.38,80.05 146.38,80.05 146.76,80.43 161.33,80.43 v1(162.47,81.57) SW4.12
  BOTTOM w0.102: 130.72,81.13 130.72,81.09 130.97,80.83 131.01,80.83 131.02,80.82 131.79,80.82 131.8,80.83 133.56,80.83 133.59,80.86
  BOTTOM w0.121: 130.72,81.13 130.66,81.19 130.66,81.25 129.8,82.11 129.31,82.11 129.01,81.81 129.01,79.61 129.02,79.6 129.02,77.08 128.89,76.95 128.38,76.95 128.26,77.08 128.26,83.4 128.13,83.53 127.19,83.53 126.83,83.89 106.37,83.89 106.03,84.22 99.08,84.22 98.18,83.33 98.18,82.97 97.89,82.68 97.89,81.36 v1(97.89,81.36) ; R108.1 v1(162.47,81.57) ; 133.59,80.86 v1(134.28,80.17)
AM335X_LCD_DATA13: length 144.2
  TOP w0.102: U2.V3 92.65,79.8
  TOP w0.121: v1(161.84,62.27) 161.45,62.65 158.86,62.65 158.66,62.44 153.02,62.44 152.68,62.79 137.56,62.79 137.45,62.9 132.18,62.9 v1(132.13,62.85) ; 92.65,79.8 92.74,79.9 93.07,79.9 93.17,79.8 94.33,79.8 95.54,78.59 97,78.59 v1(97.26,78.33) ; R258.2 127.17,81.32 126.45,81.32 126.4,81.36 125.69,81.36 v1(125.13,80.81) 125.13,81.8 125.01,81.93 124.5,81.93 124.37,81.8 124.37,80.48 124.24,80.35 123.89,80.35 123.76,80.48 123.76,81.52 123.63,81.65 116.57,81.65 116.45,81.52 116.45,81.06 116.57,80.94 122.8,80.94 122.92,80.81 122.92,80.48 122.8,80.35 108.34,80.35 108.22,80.22 108.22,79.84 108.34,79.72 113.4,79.72 113.52,79.59 113.52,79.25 113.4,79.13 108.37,79.13 108.24,79 108.24,76.93 108.11,76.8 102.53,76.8 101.95,77.38 101.95,78.29 101.83,78.42 101.15,78.42 101.03,78.29 101.03,77.41 v1(101,77.38) ; v1(161.07,79.03) v1(162.47,79.03) SW4.11
  BOTTOM w0.121: v1(101,77.38) 100.56,77.38 100.3,77.64 100.3,77.88 99.85,78.33 v1(97.26,78.33) ; v1(162.47,79.03) R109.1 ; v1(161.84,62.27) 161.84,63.04 161.27,63.6 161.27,78.83 v1(161.07,79.03) ; v1(132.13,62.85) 132.13,71.91 127.37,76.67 127.37,79.96 127.03,80.3 125.64,80.3 v1(125.13,80.81)
AM335X_LCD_DATA14: length 94.5
  TOP w0.102: U2.V4 91.97,80.43 93.22,80.43 ; 135.17,78.27 137.86,78.27 138.04,78.09
  TOP w0.121: SW4.10 v1(162.47,76.49) 161.55,76.49 160.28,77.76 150.25,77.76 149.99,78.02 142.36,78.02 142.23,77.89 141.38,77.89 R260.2 140.25,77.76 139.61,77.76 139.41,77.96 138.16,77.96 138.04,78.09 ; v1(134.53,78.4) 135.04,78.4 135.17,78.27 ; v1(98.46,82.59) 96.48,80.6 95.64,80.6 95.6,80.56 95.23,80.56 95.11,80.43 93.22,80.43
  BOTTOM w0.121: v1(98.46,82.59) 98.46,82.9 98.72,83.16 98.72,83.51 99.18,83.97 105.93,83.97 106.26,83.64 126.22,83.64 126.34,83.51 126.34,80.68 126.47,80.55 126.94,80.55 127.06,80.68 127.06,82.94 127.19,83.07 127.8,83.07 127.93,82.94 127.93,76.87 131.28,73.52 134.02,73.52 134.59,74.09 134.59,77.9 134.53,77.95 v1(134.53,78.4) ; R110.1 v1(162.47,76.49)
AM335X_LCD_DATA15: length 145.3
  TOP w0.102: v2(90.6,81) U2.T5
  TOP w0.121: v1(127.67,84.62) 127.16,85.13 125.39,85.13 125.24,84.98 125.24,84.64 125.33,84.55 126.98,84.55 R254.2 ; v1(164.5,72.43) 164.5,73.7 SW4.9 v1(162.47,73.95) ; v1(162.09,63.41) 160.43,63.41 160.11,63.72 158.89,63.72 158.1,62.94 153.41,62.94 152.63,63.72 142.83,63.72 142.39,63.28 138.21,63.28 137.83,63.66 v1(135.04,63.66)
  BOTTOM w0.095: 133.64,83.35 133.59,83.35
  BOTTOM w0.102: v2(90.6,81) 91.1,81 91.58,80.52 92.97,80.52 ; 130.72,83.48 130.85,83.35 133.59,83.35
  BOTTOM w0.121: v1(164.5,72.43) 166.41,70.52 166.41,65.65 166.2,65.44 162.04,65.44 161.78,65.18 161.78,63.72 v1(162.09,63.41) ; v1(135.04,63.66) 135.04,69.86 134.83,70.06 134.83,71.56 135.04,71.77 135.04,82.71 134.4,83.35 133.64,83.35 ; v1(162.47,73.95) R111.1 ; 92.97,80.52 93.95,80.52 94.53,81.09 94.53,81.7 94.84,82.01 96.87,82.01 97.54,82.68 97.89,83.03 97.89,83.38 98.97,84.47 106.14,84.47 106.47,84.14 125.54,84.14 125.67,84.26 125.67,84.72 125.54,84.85 116.52,84.85 116.39,84.98 116.39,86.75 116.52,86.88 126.96,86.88 127.67,86.17 127.67,85.9 127.79,85.78 128.52,85.78 128.64,85.66 128.64,85.41 128.52,85.29 127.79,85.29 127.67,85.17 v1(127.67,84.62) 130.34,84.62 130.59,84.37 130.59,83.6 130.72,83.48
AM335X_LCD_HSYNC: length 68.6
  TOP w0.102: v2(89.8,81) U2.R5
  TOP w0.121: v1(98.72,80.17) 98.72,77.51 100.41,75.81 113.8,75.81 113.93,75.68 113.93,75.37 114.06,75.25 121.01,75.25 121.14,75.12 121.14,73.77 121.26,73.65 125.82,73.65 125.94,73.77 125.94,74.1 125.82,74.23 121.93,74.23 121.8,74.36 121.8,75.18 121.93,75.3 122.74,75.3 122.87,75.18 122.87,74.92 123,74.79 123.86,74.79 123.99,74.92 123.99,75.18 124.12,75.3 125.13,75.3 125.26,75.18 125.26,74.9 125.39,74.77 126.61,74.77 126.73,74.65 126.73,73.7 126.86,73.57 133.46,73.57 133.68,73.79 133.68,73.96 133.43,74.21 127.85,74.21 127.67,74.38 R272.2
  BOTTOM w0.102: 93.29,80.27 91.13,80.27 90.78,80.62 90.18,80.62 v2(89.8,81)
  BOTTOM w0.121: 93.29,80.27 95.48,80.27 95.57,80.17 v1(98.72,80.17)
AM335X_LCD_PCLK: length 71
  TOP w0.102: U2.V5 92.26,80.94 93,80.94
  TOP w0.121: 93,80.94 94.43,80.94 95.06,81.57 v1(95.16,81.57) ; v1(99.41,80.94) 99.59,80.76 100.8,80.76 100.93,80.63 100.93,79.59 101.05,79.46 102.75,79.46 102.88,79.34 102.88,78.95 102.75,78.83 100.29,78.83 100.16,78.95 100.16,79.31 100.04,79.44 99.38,79.44 99.03,79.09 99.03,77.54 100.24,76.33 101.57,76.33 101.7,76.2 101.7,76.19 101.82,76.06 113.5,76.06 113.63,76.19 113.63,76.64 113.75,76.77 124.04,76.77 124.17,76.64 124.17,76.29 124.04,76.16 114.54,76.16 114.41,76.03 114.41,75.68 114.54,75.55 124.78,75.55 124.9,75.68 124.9,76.11 125.03,76.24 v1(125.89,76.24) 126.34,76.24 126.34,76.24 127.17,76.24 R269.2
  BOTTOM w0.121: v1(95.16,81.57) 96.71,81.57 97.47,80.81 98.07,80.81 98.21,80.95 98.21,81.06 98.47,81.32 99.03,81.32 v1(99.41,80.94)
AM335X_LCD_VSYNC: length 68.7
  TOP w0.102: 133.59,79.46 133.51,79.54 130.72,79.54 ; 93,81.83 91.35,81.83 91,81.47 U2.U5 ; 137.72,74.47 138,74.47
  TOP w0.121: v1(99.4,82.56) 98.93,83.03 98.27,83.03 97.25,82.01 94.45,82.01 94.39,81.95 93.33,81.95 93.2,81.83 93,81.83 ; 137.72,74.47 135.47,74.47 134.27,74.47 133.83,74.91 133.83,79.22 133.59,79.46 ; 138,74.47 138.15,74.62 139.5,74.62 139.65,74.46 139.83,74.46 139.93,74.37 139.93,73.82 140.05,73.7 140.75,73.7 140.88,73.82 R271.2 ; 130.72,79.54 130.34,79.54 130.09,79.29 126.53,79.29 v1(126.02,79.79)
  BOTTOM w0.121: v1(126.02,79.79) 125.89,79.67 124.47,79.67 124.34,79.79 124.34,82.61 124.47,82.74 125.06,82.74 125.18,82.61 125.18,81.67 125.31,81.55 125.97,81.55 126.1,81.67 126.1,83.27 125.97,83.39 106.16,83.39 105.83,83.73 99.28,83.73 98.97,83.41 98.97,83 v1(99.4,82.56)
AM335X_MCASP0_ACLKR: length 41.3
  TOP w0.102: U2.B12 78.65,87.35 77.75,87.35 77.58,87.52
  TOP w0.121: v1(65.85,105.19) 65.88,105.16 69.73,105.16 70.4,105.83 77.25,105.83 R218.2 ; v1(66.14,91.16) 66.33,90.97 68.03,90.97 69.36,89.65 74.51,89.65 75.89,88.26 76.46,88.26 77.21,87.52 77.58,87.52
  BOTTOM w0.121: v1(65.85,105.19) 65.85,91.45 v1(66.14,91.16)
AM335X_MCASP0_ACLKX: length 54.8
  TOP w0.102: 77.63,87.8 U2.A13
  TOP w0.121: 77.63,87.8 77.28,87.8 76.57,88.51 76,88.51 74.61,89.9 69.77,89.9 v1(69.48,90.18) ; R194.2 v1(87.54,120.71)
  LY3 w0.133: v1(78.07,120.36) 87.18,120.36 v1(87.54,120.71)
  LY4 w0.133: v1(69.48,90.18) 70.88,91.58 70.88,93.61 72.25,94.98 72.25,98.94 71.64,99.55 71.64,106.54 75.05,109.95 75.05,114.24 78.65,117.84 78.65,119.77 v1(78.07,120.36)
AM335X_MCASP0_AHCLKR: length 35.3
  TOP w0.102: v2(80.2,87.4) U2.C12
  TOP w0.121: R211.1 v1(71.67,111.47)
  LY4 w0.133: v1(69.2,91.47) 69.2,94.88 71.13,96.81 71.13,106.54 71.67,107.07 v1(71.67,111.47)
  BOTTOM w0.102: 77.1,88.24 77.32,88.24 78.52,87.03 79.86,87.03 80.2,87.38 v2(80.2,87.4)
  BOTTOM w0.121: v1(69.2,91.47) 69.2,91.42 69.58,91.05 70.24,91.05 71.7,89.58 73.05,88.24 77.1,88.24
AM335X_MCASP0_AHCLKX: length 59
  TOP w0.102: U2.A14 77.55,88.6
  TOP w0.121: v1(57.31,93) 58.84,93 59.03,92.81 61.44,92.81 62.45,93.82 63.84,93.82 64.46,93.19 64.86,93.19 66.19,91.86 67.85,91.86 68.93,90.78 70.5,90.78 70.88,90.39 74.88,90.39 76.26,89.01 76.84,89.01 77.25,88.6 77.55,88.6 ; v1(58.53,115.63) 49.26,115.63 48.22,114.59 R234.2
  BOTTOM w0.121: v1(58.53,115.63) 58.84,115.32 58.84,114.98 58.85,114.98 58.85,110.16 57.57,108.88 57.57,94.27 57.31,94.02 v1(57.31,93)
AM335X_MCASP0_AXR0: length 49.5
  TOP w0.102: v2(81,87.4) U2.D12
  LY4 w0.133: v1(79.03,122.85) 70.01,113.83 70.01,99.35 69.52,98.86 v1(69.51,98.86)
  BOTTOM w0.102: 77.05,89.47 78.94,89.47 79.03,89.38 79.6,89.38 79.79,89.19 79.79,88.75 79.92,88.62 80.04,88.62 80.04,88.62 80.36,88.62 80.58,88.4 80.58,88.02 81,87.6 v2(81,87.4)
  BOTTOM w0.121: v1(69.51,98.86) 69.36,98.72 69.36,95.92 69.86,95.42 69.86,94.03 70.74,93.15 70.74,92.29 73.56,89.47 77.05,89.47 ; R203.1 v1(79.03,122.85)
AM335X_MCASP0_AXR1: length 49.8
  TOP w0.102: v2(80.2,88.2) U2.D13
  TOP w0.121: v1(64.22,121.5) 64.15,121.58 R227.2
  BOTTOM w0.102: v2(80.2,88.2) 80,88.2 79.59,88.61 78.5,88.61 78.13,88.98 73.35,88.98 73.32,89.01
  BOTTOM w0.121: 73.32,89.01 70.16,92.18 70.05,92.18 69.48,92.75 69.48,95.26 68.63,96.11 68.63,102.82 69.73,103.92 69.73,105.8 69.13,106.41 69.13,116.6 v1(64.22,121.5)
AM335X_MCASP0_FSR: length 30
  TOP w0.102: v2(79.4,88.2) U2.C13
  TOP w0.121: v1(69.25,104.27) 69.28,104.3 70.65,104.3 72.68,102.27
  BOTTOM w0.102: 77.1,88.73 77.81,88.73 78.35,88.2 v2(79.4,88.2)
  BOTTOM w0.121: 77.1,88.73 73.25,88.73 71.91,90.07 71.91,90.07 70.8,91.18 70.05,91.93 69.13,91.93 68.77,92.29 68.77,94.14 69.12,94.49 69.12,95.22 68.38,95.95 68.38,103.43 69.21,104.27 v1(69.25,104.27)
AM335X_MCASP0_FSX: length 58.8
  TOP w0.102: U2.B13 78.63,88.18 77.63,88.18
  TOP w0.121: v1(81.22,118.45) 74.7,118.45 74.5,118.25 67.89,118.25 v1(67.16,117.51) ; v1(70.29,90.34) 70.49,90.14 74.78,90.14 76.16,88.76 76.67,88.76 77.25,88.18 77.63,88.18
  BOTTOM w0.121: v1(67.16,117.51) 67.16,116.56 68.8,114.91 68.8,104.21 68.13,103.54 68.13,95.71 68.87,94.97 68.87,94.6 68.52,94.25 68.52,91.54 69.26,90.8 69.83,90.8 v1(70.29,90.34) ; R199.1 82.46,121.83 81.63,121 81.63,118.82 81.27,118.45 v1(81.22,118.45)
AM335X_MII1_COL: length 14.4
  TOP w0.102: v2(83.4,90.6) U2.H16
  TOP w0.121: R231.2 81.77,101.74 v1(82.23,102.2)
  LY4 w0.102: v2(83.4,90.6) 83.4,90.79 83.53,90.92 83.53,91.43 84.58,92.48 84.58,93.1
  LY4 w0.133: v1(82.23,102.2) 82.28,102.2 83.3,101.18 83.3,95.17 84.58,93.89 84.58,93.1
AM335X_MII1_CRS: length 75.2
  TOP w0.102: U2.H17 83.35,91.45 83.35,92.9
  TOP w0.121: v1(84.14,131.43) 62.14,131.43 61.02,132.55 59.24,132.55 58.65,133.13 R235.2 ; v1(82.31,93.84) 82.31,93.7 82.43,93.57 83.1,93.57 83.36,93.31 83.36,92.96 83.35,92.95 83.35,92.9
  LY4 w0.133: v1(82.31,93.84) 82.78,94.32 82.78,99.14 81.51,100.4 81.51,103.2 82.47,104.15 82.47,113.21 81.98,113.7 81.98,117.09 83.86,118.97 83.86,131.15 v1(84.14,131.43)
AM335X_MII1_MDIO_CLK: length 44.1
  TOP w0.102: U2.M18 87.11,91.91 87.11,93.54
  TOP w0.121: v1(86.95,95.08) 86.93,95.08 86.7,94.85 86.7,93.96 87.11,93.54 ; R195.1 v1(87.29,131.66)
  LY4 w0.133: v1(86.95,95.08) 86.95,98.86 86.91,98.9 86.91,101.11 87.05,101.25 87.05,123.43 88.76,125.14 88.76,131.74 88.44,132.06 87.71,132.06 87.31,131.66 v1(87.29,131.66)
AM335X_MII1_MDIO_DATA: length 44.4
  TOP w0.102: 87.36,92.9 87.36,91.36 U2.M17
  TOP w0.121: v1(87.14,94.14) 87.36,93.92 87.36,92.9 ; v1(88.25,131.61) 88.43,131.79 R192.1
  LY4 w0.133: v1(88.25,131.61) 88.25,130.67 88.5,130.42 88.5,125.24 86.79,123.53 86.79,101.44 85.64,100.29 85.64,95.31 86.8,94.14 v1(87.14,94.14)
AM335X_MII1_REFCLK: length 10.1
  TOP w0.102: U2.H18 83.8,92.87 83.8,92.87 v1(83.8,93.31)
  BOTTOM w0.121: R188.1 85.39,99.72 85.39,95.68 84.72,95.01 v1(83.8,93.31)
AM335X_MII1_RXCLK: length 9.8
  TOP w0.102: 86,93.1 86,92 U2.L18
  TOP w0.121: R162.2 86.67,100.04 86.86,99.85 86.86,99.42 86.52,99.07 86.52,98.79 87.03,98.28 87.03,96.18 86.67,95.82 86.03,95.82 85.72,95.52 85.72,93.38 86,93.1
AM335X_MII1_RXD0: length 9.9
  TOP w0.102: v2(87.4,90.6) U2.M16
  TOP w0.121: R190.1 89.7,96.18 v1(88.07,94.55)
  BOTTOM w0.102: v2(87.4,90.6) 87.4,92.05 87.48,92.12 87.93,92.12 88.01,92.05 88.01,91.84 88.09,91.76 88.54,91.76 88.61,91.84 88.61,92.92
  BOTTOM w0.121: v1(88.07,94.55) 88.54,94.55 88.61,94.47 88.61,92.92
AM335X_MII1_RXD1: length 9.7
  TOP w0.102: v2(86.6,89.8) U2.L15
  BOTTOM w0.102: 87.28,92.35 87.02,92.09 87.02,90.19 86.62,89.8 v2(86.6,89.8)
  BOTTOM w0.121: 87.28,92.35 88.13,92.35 88.21,92.42 88.21,93.93 88.13,94.01 87.71,94.01 87.63,94.09 87.63,94.77 88.1,95.24 88.1,97.01 88.05,97.07
AM335X_MII1_RXD2: length 10
  TOP w0.102: v2(86.6,90.6) U2.L16
  BOTTOM w0.121: 87.03,97.07 87.06,97.07 87.85,96.27 87.85,95.35 87.09,94.58 86.7,94.58 86.6,94.48 86.6,93.77 86.68,93.69 87.53,93.69 87.61,93.61 87.61,92.65 87.53,92.57 86.68,92.57 86.6,92.49 v2(86.6,90.6)
AM335X_MII1_RXD3: length 9.7
  TOP w0.102: 86.8,92.87 86.34,92.87 86.23,92.76 86.23,92.35 86.34,92.25 86.55,92.25 86.67,92.13 86.67,91.25 86.42,91 U2.L17
  TOP w0.121: R158.2 87.28,96.78 87.28,96.08 86.77,95.57 86.14,95.57 86.06,95.5 86.06,94.83 86.14,94.76 86.37,94.76 86.45,94.68 86.45,94.25 86.37,94.18 86.05,94.18 85.97,94.1 85.97,93.62 86.1,93.5 86.8,93.5 86.88,93.42 86.88,92.95 86.8,92.87
AM335X_MII1_RXDV: length 10.1
  TOP w0.102: 84.24,92.9 84.24,91.36 U2.J17
  TOP w0.121: R168.2 82.72,97.59 82.72,97.79 82.58,97.94 82.33,97.94 82.24,97.85 82.24,97.42 82.38,97.29 82.38,96.33 82.5,96.2 82.65,96.2 82.77,96.07 82.77,93.97 82.9,93.84 84.12,93.84 84.24,93.72 84.24,92.9
AM335X_MII1_RXERR: length 18.2
  TOP w0.102: v2(84.2,89.8) U2.J15
  TOP w0.121: v1(84.01,105.22) 83.65,105.57 R237.2
  LY4 w0.102: 84.85,92.95 84.85,92.24 83.82,91.21 83.82,90.19 84.2,89.81 v2(84.2,89.8)
  LY4 w0.133: v1(84.01,105.22) 83.56,104.77 83.56,95.28 84.85,93.99 84.85,92.95
AM335X_MII1_TXCLK: length 9.9
  TOP w0.102: U2.K18 85.41,91.81 85.41,92.92
  TOP w0.121: 85.41,92.92 85.23,93.1 85.23,95.05 85.1,95.18 84.59,95.18 84.46,95.05 84.46,94.75 84.33,94.63 83.81,94.63 83.66,94.78 83.66,96.16 84.06,96.56 84.22,96.56 84.35,96.43 84.35,96.22 84.47,96.09 84.73,96.09 84.86,96.22 84.86,96.85 85.05,97.04 R160.2
AM335X_MII1_TXD0: length 9.7
  TOP w0.102: 85.76,92.9 85.76,91.36 U2.K17
  TOP w0.121: 85.76,92.9 85.76,92.95 85.48,93.24 85.48,96.29 86.01,96.83 86.01,98.29 85.64,98.67 R174.2
AM335X_MII1_TXD1: length 9.7
  TOP w0.102: v2(85.8,90.6) U2.K16
  TOP w0.121: R172.2 86.52,96.3 v1(86.48,96.26)
  BOTTOM w0.102: 85.8,92.9 85.8,92.24 85.72,92.17 84.57,92.17 84.49,92.09 84.49,91.28 84.57,91.2 85.72,91.2 85.8,91.12 v2(85.8,90.6)
  BOTTOM w0.121: v1(86.48,96.26) 86.32,96.1 86.32,95.44 85.8,94.92 85.8,92.9
AM335X_MII1_TXD2: length 10.1
  TOP w0.102: v2(85.8,89.8) U2.K15
  TOP w0.121: R166.2 88.68,96.81 v1(87.41,95.54)
  BOTTOM w0.102: v2(85.8,89.8) 86.18,90.18 86.18,92.9
  BOTTOM w0.121: v1(87.41,95.54) 87.41,95.89 87.34,95.97 86.86,95.97 86.78,95.89 86.78,95.54 86.18,94.94 86.18,92.9
AM335X_MII1_TXD3: length 9.6
  TOP w0.102: 84.6,92.9 U2.J18
  TOP w0.121: R170.2 83.22,99 83.3,98.92 83.68,98.92 83.76,98.85 83.76,96.96 83.1,96.3 83.1,94.25 83.25,94.09 84.21,94.09 84.6,93.71 84.6,92.9
AM335X_MII1_TXEN: length 9.6
  TOP w0.102: 85,92.9 85,89.93 84.9,89.83 84.75,89.83 84.64,89.93 84.64,90.16 U2.J16
  TOP w0.121: 84.37,97.07 84.21,97.07 83.34,96.2 83.34,94.55 83.55,94.35 84.38,94.35 84.93,93.8 84.93,92.97 85,92.9
AM335X_MMC_CLK: length 64.7
  TOP w0.102: 82.61,92.72 82.61,91.39 U2.G17
  TOP w0.121: v1(82.33,95.7) 82.25,95.7 81.67,95.12 81.67,93.66 82.61,92.72
  BOTTOM w0.121: v1(82.33,95.7) 82.33,95.85 82.62,96.14 82.62,98.65 81.73,99.54 81.73,100.73 81.23,101.23 81.23,117.04 81.88,117.7 81.88,120.87 83.63,122.62 83.63,129.6 83.43,129.79 82.74,129.79 82.61,129.92 82.61,130.15 82.74,130.27 83.43,130.27 83.56,130.39 83.56,130.63 83.43,130.75 82.81,130.75 82.69,130.88 82.69,131.12 82.81,131.24 83.43,131.24 83.56,131.36 83.56,131.6 83.43,131.72 82.81,131.72 82.69,131.84 82.69,132.08 82.81,132.2 83.43,132.2 83.56,132.32 83.56,132.56 83.43,132.69 82.81,132.69 82.69,132.81 82.69,133.05 82.81,133.17 83.43,133.17 83.56,133.29 83.56,133.53 83.43,133.65 82.81,133.65 82.69,133.77 82.69,134.01 82.81,134.13 83.43,134.13 83.56,134.25 83.56,134.5 83.43,134.62 82.81,134.62 82.69,134.74 82.69,134.98 82.81,135.1 83.43,135.1 83.56,135.22 83.56,135.47 82.71,136.31 82.71,142.66 R197.2
AM335X_MMC_CMD: length 79.4
  TOP w0.102: 83,92.69 U2.G18
  TOP w0.121: v1(90.16,143.7) 89.98,143.52 85.42,143.52 85.4,143.55 v1(81.95,143.55) ; 83,92.69 82.94,92.74 82.94,93.02 82.91,93.05 v1(82.91,93.13)
  BOTTOM w0.102: 84.59,92.9 84.52,92.82 83.14,92.82 83.06,92.9
  BOTTOM w0.121: v1(90.16,143.7) 90.03,143.7 89.9,143.57 89.9,128.59 90.03,128.46 90.44,128.46 90.56,128.59 90.56,134.38 90.69,134.5 91.14,134.5 91.26,134.38 91.26,133.51 91.55,133.23 91.55,132.45 91.26,132.16 91.26,122.13 89.06,119.93 89.06,106.03 85.9,102.86 85.9,101.9 85.91,101.89 85.91,96.94 85.77,96.8 85.77,95.71 85.03,94.96 85.03,93.33 84.59,92.9 ; R200.2 v1(81.95,143.55) ; 83.06,92.9 82.91,93.05 v1(82.91,93.13)
AM335X_MMC_D0: length 60.2
  TOP w0.102: v2(82.6,90.6) U2.G16
  BOTTOM w0.102: v2(82.6,90.6) 82.6,92.4
  BOTTOM w0.121: 82.6,92.4 81.7,93.3 81.7,95.69 82.38,96.37 82.38,98.55 81.48,99.44 81.48,99.64 81.48,100.57 80.98,101.08 80.98,117.82 80.66,118.15 80.66,121.3 81.77,122.41 81.77,124.85 81.51,125.12 81.51,131.66 81.63,131.78 82.26,131.78 82.38,131.9 82.38,132.14 82.26,132.26 81.63,132.26 81.51,132.38 81.51,132.63 81.63,132.75 82.26,132.75 82.38,132.87 82.38,133.11 82.26,133.23 81.63,133.23 81.26,133.6 81.26,135.22 80.24,136.24 80.24,140.69 80.36,140.81 80.36,142.83 79.77,143.42 79.18,143.42 79.15,143.45 R204.2
AM335X_MMC_D1: length 71.5
  TOP w0.102: v2(82.6,89.8) U2.G15
  TOP w0.121: v1(84.82,141.74) 81.98,141.74 80.76,142.96 72.12,142.96 v1(71.64,143.45)
  LY4 w0.133: v1(83.15,116.09) 83.58,115.66 83.58,108.4 86.34,105.63 v1(86.34,102.08)
  BOTTOM w0.102: v2(82.6,89.8) 83.02,90.22 83.02,90.82
  BOTTOM w0.121: v1(86.34,102.08) 86.34,96.86 86.04,96.56 86.04,95.63 85.38,94.97 85.38,93.34 83.44,91.39 83.44,91.24 83.02,90.82 ; v1(84.82,141.74) 84.82,140.21 84.93,140.11 84.93,129.78 85.95,128.75 85.95,123.9 83.15,121.09 v1(83.15,116.09) ; R400.2 v1(71.64,143.45)
AM335X_MMC_D2: length 89.5
  TOP w0.102: U2.F18 82.2,92.79
  TOP w0.121: v1(79.92,142.4) 78.82,142.4 78.7,142.28 78.7,141.57 78.58,141.45 78.33,141.45 78.21,141.57 78.21,142.28 78.09,142.4 77.85,142.4 77.73,142.28 77.73,141.57 77.61,141.45 77.37,141.45 77.25,141.57 77.25,142.28 77.13,142.4 76.89,142.4 76.77,142.28 76.77,141.57 76.65,141.45 76.4,141.45 76.28,141.57 76.28,142.28 76.16,142.4 75.92,142.4 75.8,142.28 75.8,141.57 75.68,141.45 75.44,141.45 75.32,141.57 75.32,142.28 75.2,142.4 74.96,142.4 74.84,142.28 74.84,141.57 74.71,141.45 74.47,141.45 74.35,141.57 74.35,142.28 74.23,142.4 73.99,142.4 73.87,142.28 73.87,141.57 73.75,141.45 73.51,141.45 73.39,141.57 73.39,142.28 73.27,142.4 73.03,142.4 72.9,142.28 72.9,141.57 72.78,141.45 72.54,141.45 72.42,141.57 72.42,142.28 72.3,142.4 72.06,142.4 71.94,142.28 71.94,141.57 71.82,141.45 71.58,141.45 71.46,141.57 71.46,142.28 71.34,142.4 71.1,142.4 70.97,142.28 70.97,141.57 70.85,141.45 70.61,141.45 70.49,141.57 70.49,142.28 70.37,142.4 69.88,142.4 69.76,142.28 69.76,141.64 69.64,141.52 69.4,141.52 69.28,141.64 69.28,142.28 69.16,142.4 68.92,142.4 68.8,142.28 68.8,141.64 68.68,141.52 68.44,141.52 68.32,141.64 68.32,142.28 68.19,142.4 67.95,142.4 67.83,142.28 67.83,141.64 67.71,141.52 67.47,141.52 67.35,141.64 67.35,142.28 67.23,142.4 67.14,142.4 67.02,142.53 67.02,143.32 67.14,143.45 v1(69.23,143.45) ; v1(81.76,96.43) 81.56,96.24 81.56,95.44 81.42,95.3 81.42,93.56 82.2,92.79
  BOTTOM w0.121: v1(81.76,96.43) 81.75,96.43 81.09,97.09 81.09,99.07 80.87,99.28 80.87,100.43 80.49,100.82 80.49,106.82 79.38,107.93 79.38,120.78 80.56,121.96 80.56,124.75 81.02,125.21 81.02,129.75 80.37,130.4 80.37,134.77 v1(80.31,134.83) 80.31,135.28 79.67,135.92 79.67,141.25 79.41,141.51 79.41,141.9 v1(79.92,142.4) ; R215.2 v1(69.23,143.45)
AM335X_MMC_D3: length 87.1
  TOP w0.121: v1(81.93,97.11) 81.69,97.11 81.31,96.73 81.31,95.54 81.18,95.41 81.18,93.46 81.78,92.86 81.78,91.42 U2.F17 ; v1(66.36,142.94) 66.36,141.9 67.05,141.2 68.75,141.2 68.87,141.08 68.87,140.93 69,140.81 69.24,140.81 69.36,140.93 69.36,141.08 69.48,141.2 69.72,141.2 69.84,141.08 69.84,140.93 69.96,140.81 70.2,140.81 70.32,140.93 70.32,141.08 70.44,141.2 70.68,141.2 70.81,141.08 70.81,140.93 70.93,140.81 71.17,140.81 71.29,140.93 71.29,141.08 71.41,141.2 71.65,141.2 71.77,141.08 71.77,140.93 71.89,140.81 72.13,140.81 72.25,140.93 72.25,141.08 72.37,141.2 72.61,141.2 72.74,141.08 72.74,140.93 72.86,140.81 73.1,140.81 73.22,140.93 73.22,141.08 73.34,141.2 73.58,141.2 73.7,141.08 73.7,140.93 73.82,140.81 74.06,140.81 74.18,140.93 74.18,141.08 74.3,141.2 74.55,141.2 74.67,141.08 74.67,140.93 74.79,140.81 75.03,140.81 75.15,140.93 75.15,141.08 75.27,141.2 75.51,141.2 75.63,141.08 75.63,140.93 75.75,140.81 75.99,140.81 76.11,140.93 76.11,141.08 76.23,141.2 76.48,141.2 76.6,141.08 76.6,140.93 76.72,140.81 76.96,140.81 77.08,140.93 77.08,141.08 77.2,141.2 77.44,141.2 77.56,141.08 77.56,140.93 77.68,140.81 77.92,140.81 78.04,140.93 78.04,141.08 78.16,141.2 78.41,141.2 78.53,141.08 78.53,140.93 78.65,140.81 78.89,140.81 79.01,140.93 79.01,141.08 79.13,141.2 79.41,141.2 79.83,141.62 v1(79.92,141.62)
  BOTTOM w0.121: v1(66.36,142.94) 66.36,143.29 66.46,143.39 R219.2 ; v1(79.92,141.62) 79.99,141.55 79.99,135.98 80.81,135.16 80.81,134.65 80.62,134.45 80.62,130.67 81.26,130.02 81.26,122.28 79.63,120.65 79.63,120.4 79.75,120.28 80.13,120.28 80.25,120.16 80.25,119.92 80.13,119.8 79.75,119.8 79.63,119.68 79.63,119.44 79.75,119.32 80.13,119.32 80.25,119.19 80.25,118.95 80.13,118.83 79.75,118.83 79.63,118.71 79.63,118.47 79.75,118.35 80.13,118.35 80.25,118.23 80.25,117.99 80.13,117.87 79.75,117.87 79.63,117.75 79.63,117.51 79.75,117.39 80.13,117.39 80.25,117.26 80.25,117.02 80.13,116.9 79.75,116.9 79.63,116.78 79.63,116.54 79.75,116.42 80.13,116.42 80.25,116.3 80.25,116.06 80.13,115.94 79.75,115.94 79.63,115.82 79.63,115.58 79.75,115.45 80.13,115.45 80.25,115.33 80.25,115.09 80.13,114.97 79.75,114.97 79.63,114.85 79.63,114.61 79.75,114.49 80.13,114.49 80.25,114.37 80.25,114.13 80.13,114.01 79.75,114.01 79.63,113.89 79.63,113.64 79.75,113.52 80.13,113.52 80.25,113.4 80.25,113.16 80.13,113.04 79.75,113.04 79.63,112.92 79.63,112.68 79.75,112.56 80.13,112.56 80.25,112.44 80.25,112.2 80.13,112.08 79.75,112.08 79.63,111.96 79.63,111.71 79.75,111.59 80.13,111.59 80.25,111.47 80.25,111.23 80.13,111.11 79.75,111.11 79.63,110.99 79.63,110.75 79.75,110.63 80.13,110.63 80.25,110.51 80.25,110.27 80.13,110.15 79.75,110.15 79.63,110.03 79.63,109.78 79.75,109.66 80.13,109.66 80.25,109.54 80.25,109.3 80.13,109.18 79.75,109.18 79.63,109.06 79.63,108.03 80.73,106.92 80.73,100.97 80.98,100.72 80.99,100.72 81.24,100.47 81.24,99.75 81.24,99.3 81.34,99.2 81.34,97.76 81.93,97.16 v1(81.93,97.11)
AM335X_OSC0_IN: length 20.2
  TOP w0.102: U2.V10 92.47,85.4 92.78,85.1 94.38,85.1
  TOP w0.121: 94.38,85.1 94.86,85.58 98.45,85.58 99.85,84.18 99.85,82.49 R7.2 101.41,80.94 101.41,80.76 C4.1 106.74,80.15 106.97,79.92 106.97,78.65 Y2.3
